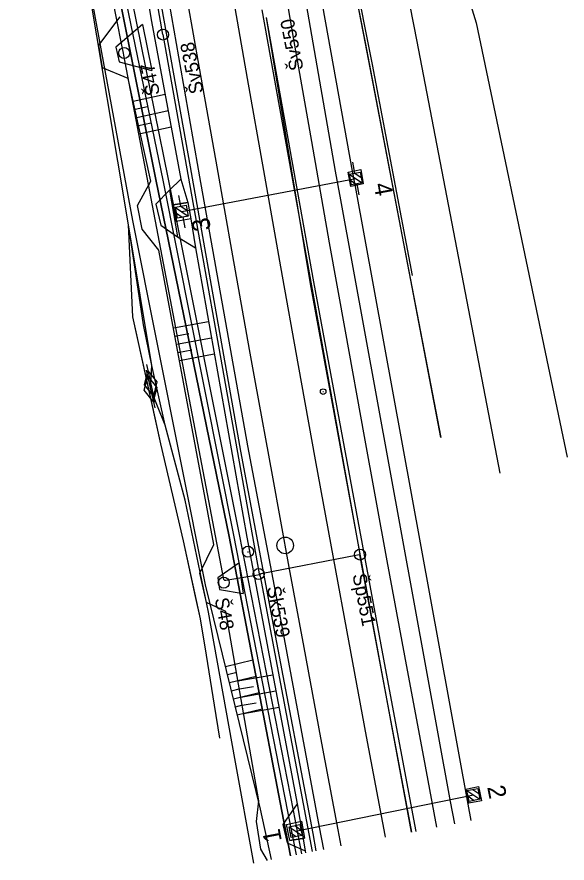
# Model space of a CAD drawing. Extents: x -545736 to -544888, y -1122892 to -1119128.
# Drawn here: x -545053.2 to -545003.3, y -1122756.6 to -1122679.8 of the extents above; entities that cross this region are included whole.
import ezdxf

# ---------------------------------------------------------------- set-up
doc = ezdxf.new("R2010")
doc.units = 0
for name, color, linetype in [('Vrstva 1', 7, 'Continuous'), ('Vrstva 1 - Koleje', 7, 'Continuous'), ('Vrstva 11 - Trakce', 7, 'Continuous'), ('Vrstva 12', 7, 'Continuous'), ('Vrstva 12 - Trakce zaklady', 7, 'Continuous'), ('Vrstva 13', 7, 'Continuous'), ('Vrstva 19 - Staniceni', 7, 'Continuous'), ('Vrstva 28 - zabzar', 7, 'Continuous'), ('Vrstva 31', 7, 'Continuous'), ('Vrstva 32', 7, 'Continuous'), ('Vrstva 4 - Teren - stezky - prechody - plochy', 7, 'Continuous'), ('Vrstva 43', 7, 'Continuous'), ('Vrstva 44', 7, 'Continuous'), ('Vrstva 48', 7, 'Continuous'), ('Vrstva 49', 7, 'Continuous'), ('Vrstva 50', 7, 'Continuous'), ('Vrstva 7 - Namezniky-vystroj', 7, 'Continuous')]:
    doc.layers.add(name, color=color, linetype=linetype)

msp = doc.modelspace()

# ---------------------------------------------------------------- linework, layer by layer
at = {"layer": 'Vrstva 1'}
for points in [[(-545068.904, -1122411.876), (-545066.819, -1122423.364), (-545063.507, -1122440.549), (-545060.331, -1122456.897), (-545057.192, -1122473.275), (-545054.444, -1122488.508), (-545052.57, -1122500.819), (-545051.42, -1122511.592), (-545050.311, -1122520.98), (-545049.375, -1122526.795), (-545046.137, -1122542.925), (-545043.214, -1122557.71), (-545039.903, -1122574.434), (-545036.419, -1122592.255), (-545033.982, -1122604.761), (-545029.871, -1122624.617), (-545027.294, -1122633.968), (-545025.013, -1122641.762), (-545022.676, -1122652.428), (-545020.046, -1122666.027), (-545016.909, -1122682.055), (-545009.383, -1122721.21)], [(-545016.12, -1122665.438), (-545011.513, -1122680.374), (-545003.284, -1122719.736)]]:
    msp.add_lwpolyline(points, dxfattribs=at)
at = {"layer": 'Vrstva 1 - Koleje'}
for points in [[(-545023.767, -1122755), (-545024.043, -1122753.548), (-545025.612, -1122745.204), (-545027.14, -1122737.009), (-545028.487, -1122729.713), (-545030.01, -1122721.384), (-545031.532, -1122712.985), (-545032.069, -1122710.001), (-545033.588, -1122701.505), (-545035.11, -1122692.915), (-545036.637, -1122684.297), (-545038.185, -1122675.556), (-545039.699, -1122666.989), (-545041.211, -1122658.46), (-545042.758, -1122649.711), (-545044.3, -1122641.015), (-545045.323, -1122635.226), (-545046.484, -1122628.653), (-545047.761, -1122621.452), (-545049.274, -1122612.897), (-545050.721, -1122604.725), (-545052.28, -1122595.938)], [(-545015.09, -1122753.302), (-545016.134, -1122747.772), (-545018.009, -1122737.759), (-545019.601, -1122729.15), (-545021.653, -1122717.88), (-545023.38, -1122708.324), (-545024.816, -1122700.316), (-545026.431, -1122691.14), (-545028.048, -1122681.884), (-545029.659, -1122672.557), (-545031.082, -1122664.266), (-545032.373, -1122656.733), (-545033.696, -1122649.053), (-545034.644, -1122643.504), (-545035.403, -1122639.104), (-545036.316, -1122633.811), (-545037.843, -1122624.885), (-545039.388, -1122615.924), (-545041.014, -1122606.453), (-545042.699, -1122596.644)], [(-545019.74, -1122754.212), (-545019.777, -1122754.016), (-545021.46, -1122745.07), (-545023.077, -1122736.395), (-545024.44, -1122729.019), (-545026.088, -1122720.006), (-545027.636, -1122711.45), (-545029.243, -1122702.488), (-545030.788, -1122693.757), (-545032.249, -1122685.43), (-545033.701, -1122677.071), (-545035.124, -1122668.8), (-545035.413, -1122667.129), (-545036.812, -1122658.975), (-545038.248, -1122650.614), (-545039.289, -1122644.538), (-545039.869, -1122641.154), (-545040.66, -1122636.562), (-545041.029, -1122634.405), (-545042.47, -1122626.014), (-545043.93, -1122617.521), (-545045.385, -1122609.05), (-545046.733, -1122601.181)]]:
    msp.add_lwpolyline(points, dxfattribs=at)
at = {"layer": 'Vrstva 11 - Trakce'}
for p, q in [((-545022.53, -1122693.999), (-545022.71, -1122693.012)), ((-545038.214, -1122697.489), (-545022.439, -1122694.487)), ((-545023.017, -1122694.109), (-545021.88, -1122694.893)), ((-545022.921, -1122694.63), (-545022.402, -1122694.989)), ((-545022.523, -1122693.994), (-545021.948, -1122694.391)), ((-545022.351, -1122694.969), (-545022.168, -1122695.962)), ((-545038.305, -1122697.001), (-545038.485, -1122696.014)), ((-545038.298, -1122696.996), (-545037.723, -1122697.393)), ((-545038.792, -1122697.111), (-545037.655, -1122697.895)), ((-545038.696, -1122697.632), (-545038.177, -1122697.991)), ((-545038.126, -1122697.971), (-545037.943, -1122698.964)), ((-545012.362, -1122749.976), (-545011.189, -1122750.758)), ((-545011.843, -1122749.872), (-545011.293, -1122750.239)), ((-545027.903, -1122753.654), (-545011.777, -1122750.369)), ((-545012.262, -1122750.494), (-545011.705, -1122750.865)), ((-545028.484, -1122753.254), (-545027.32, -1122754.05)), ((-545028.389, -1122753.773), (-545027.837, -1122754.15)), ((-545027.963, -1122753.156), (-545027.418, -1122753.529))]:
    msp.add_line(p, q, dxfattribs=at)
for points in [[(-545022.038, -1122693.905), (-545021.857, -1122694.888), (-545022.84, -1122695.069), (-545023.021, -1122694.086)], [(-545037.813, -1122696.907), (-545037.632, -1122697.89), (-545038.615, -1122698.071), (-545038.796, -1122697.088)], [(-545011.385, -1122749.781), (-545011.189, -1122750.761), (-545012.169, -1122750.957), (-545012.365, -1122749.977)], [(-545027.504, -1122753.07), (-545027.319, -1122754.053), (-545028.302, -1122754.238), (-545028.487, -1122753.255)]]:
    msp.add_lwpolyline(points, close=True, dxfattribs=at)
at = {"layer": 'Vrstva 12'}
for points in [[(-545026.22, -1122658.509), (-545024.157, -1122669.139), (-545021.595, -1122682.153), (-545018.115, -1122700.386), (-545014.754, -1122717.969)], [(-545017.292, -1122703.282), (-545020.935, -1122684.162), (-545024.277, -1122667.282), (-545025.839, -1122658.306), (-545026.086, -1122658.352)], [(-545024.136, -1122669.136), (-545021.579, -1122682.243), (-545018.116, -1122700.384), (-545014.728, -1122717.956)]]:
    msp.add_lwpolyline(points, dxfattribs=at)
at = {"layer": 'Vrstva 12 - Trakce zaklady'}
for p, q in [((-545023.134, -1122693.91), (-545021.985, -1122693.681)), ((-545021.76, -1122694.96), (-545022.902, -1122695.206)), ((-545037.682, -1122696.647), (-545039.011, -1122696.884)), ((-545037.41, -1122698.127), (-545038.727, -1122698.372)), ((-545012.473, -1122749.852), (-545011.314, -1122749.611)), ((-545011.056, -1122750.9), (-545012.203, -1122751.117)), ((-545028.422, -1122754.51), (-545028.737, -1122753.043)), ((-545028.422, -1122754.51), (-545027.087, -1122754.284))]:
    msp.add_line(p, q, dxfattribs=at)
for points in [[(-545022.902, -1122695.206), (-545023.134, -1122693.91), (-545021.985, -1122693.681), (-545021.76, -1122694.96), (-545022.902, -1122695.206)], [(-545023.134, -1122693.91), (-545023.134, -1122693.91), (-545022.902, -1122695.206), (-545022.902, -1122695.206)], [(-545021.985, -1122693.681), (-545021.985, -1122693.681), (-545021.76, -1122694.96), (-545021.76, -1122694.96)], [(-545037.682, -1122696.647), (-545037.41, -1122698.127), (-545038.727, -1122698.372), (-545039.011, -1122696.884), (-545037.682, -1122696.647)], [(-545037.682, -1122696.647), (-545037.682, -1122696.647), (-545037.41, -1122698.127), (-545037.41, -1122698.127)], [(-545012.203, -1122751.117), (-545012.473, -1122749.852), (-545011.314, -1122749.611), (-545011.056, -1122750.9), (-545012.203, -1122751.117)], [(-545012.473, -1122749.852), (-545012.473, -1122749.852), (-545012.203, -1122751.117), (-545012.203, -1122751.117)], [(-545011.314, -1122749.611), (-545011.314, -1122749.611), (-545011.056, -1122750.9), (-545011.056, -1122750.9)], [(-545027.375, -1122752.749), (-545027.087, -1122754.284), (-545028.422, -1122754.51), (-545028.737, -1122753.043), (-545027.375, -1122752.749)], [(-545028.737, -1122753.043), (-545028.737, -1122753.043), (-545027.375, -1122752.749), (-545027.375, -1122752.749)], [(-545027.375, -1122752.749), (-545027.087, -1122754.284), (-545027.087, -1122754.284)]]:
    msp.add_lwpolyline(points, dxfattribs=at)
at = {"layer": 'Vrstva 13'}
for points in [[(-545028.35, -1122755.897), (-545029.145, -1122751.861), (-545033.916, -1122726.946), (-545040.565, -1122694.58), (-545045.437, -1122670.217), (-545050.32, -1122646.168), (-545054.473, -1122623.814), (-545058.217, -1122603.978), (-545063.836, -1122576.435), (-545069.59, -1122547.465), (-545075.408, -1122519.018), (-545078.686, -1122503.072), (-545078.31, -1122502.943)], [(-545027.819, -1122755.793), (-545028.599, -1122751.872), (-545033.511, -1122726.819), (-545039.921, -1122694.648), (-545044.959, -1122670.154), (-545049.898, -1122646.069), (-545054.001, -1122623.766), (-545057.758, -1122603.891), (-545063.364, -1122576.321), (-545069.202, -1122547.386), (-545075.005, -1122518.95), (-545078.31, -1122502.943), (-545077.905, -1122502.754), (-545074.587, -1122518.877), (-545068.787, -1122547.323), (-545062.931, -1122576.272), (-545057.246, -1122603.793), (-545053.518, -1122623.679), (-545049.43, -1122646.062), (-545044.427, -1122670.103), (-545039.459, -1122694.557), (-545033.025, -1122726.769), (-545028.137, -1122751.773), (-545027.357, -1122755.702)]]:
    msp.add_lwpolyline(points, dxfattribs=at)
at = {"layer": 'Vrstva 19 - Staniceni'}
msp.add_circle((-545028.846, -1122727.751), 0.75, dxfattribs=at)
at = {"layer": 'Vrstva 28 - zabzar'}
for p, q in [((-545041.423, -1122711.347), (-545040.657, -1122714.753)), ((-545039.73, -1122716.86), (-545040.95, -1122711.44)), ((-545041.608, -1122713.178), (-545041.296, -1122711.915)), ((-545041.443, -1122711.857), (-545040.677, -1122715.263)), ((-545041.296, -1122711.915), (-545040.472, -1122712.922)), ((-545041.628, -1122713.688), (-545041.316, -1122712.425)), ((-545041.316, -1122712.425), (-545040.492, -1122713.432)), ((-545040.472, -1122712.922), (-545040.784, -1122714.185)), ((-545040.804, -1122714.695), (-545041.628, -1122713.688)), ((-545040.784, -1122714.185), (-545041.608, -1122713.178)), ((-545040.492, -1122713.432), (-545040.804, -1122714.695))]:
    msp.add_line(p, q, dxfattribs=at)
for points in [[(-545031.702, -1122756.553), (-545033.41, -1122747.06), (-545035.8, -1122733.81), (-545037.91, -1122723.65), (-545039.73, -1122716.86), (-545041.06, -1122713.56), (-545041.04, -1122713.05), (-545040.95, -1122711.44), (-545041.68, -1122707.74), (-545043.05, -1122698.7), (-545046.9, -1122675.76), (-545050.11, -1122660.02), (-545051.04, -1122658.97), (-545052.61, -1122653.49), (-545054.9, -1122643.24), (-545056.97, -1122632.39), (-545059.36, -1122618.98), (-545062.05, -1122603.96), (-545065.13, -1122586.61)], [(-545034.78, -1122745.23), (-545035.26, -1122742.24), (-545035.97, -1122737.69), (-545036.53, -1122734.41), (-545038.07, -1122727.35), (-545040.12, -1122718.53), (-545042.66, -1122707.03), (-545043.05, -1122698.7)]]:
    msp.add_lwpolyline(points, dxfattribs=at)
at = {"layer": 'Vrstva 31'}
msp.add_lwpolyline([(-545031.702, -1122756.553), (-545033.41, -1122747.06), (-545035.8, -1122733.81), (-545037.91, -1122723.65), (-545039.73, -1122716.86), (-545040.95, -1122711.44), (-545043.05, -1122698.7), (-545046.9, -1122675.76), (-545050.11, -1122660.02), (-545051.04, -1122658.97), (-545052.61, -1122653.49), (-545054.9, -1122643.24), (-545056.97, -1122632.39), (-545059.36, -1122618.98), (-545062.05, -1122603.96), (-545065.13, -1122586.61)], dxfattribs=at)
at = {"layer": 'Vrstva 32'}
for points in [[(-545031.702, -1122756.553), (-545033.41, -1122747.06), (-545035.8, -1122733.81), (-545037.91, -1122723.65), (-545039.73, -1122716.86), (-545040.95, -1122711.44), (-545041.68, -1122707.74), (-545043.05, -1122698.7), (-545046.9, -1122675.76), (-545050.11, -1122660.02), (-545051.04, -1122658.97), (-545052.61, -1122653.49), (-545054.9, -1122643.24), (-545056.97, -1122632.39), (-545059.36, -1122618.98), (-545062.05, -1122603.96), (-545065.13, -1122586.61)], [(-545034.78, -1122745.23), (-545035.26, -1122742.24), (-545035.97, -1122737.69), (-545036.53, -1122734.41), (-545038.07, -1122727.35), (-545040.12, -1122718.53), (-545040.85, -1122715.22), (-545042.66, -1122707.03), (-545043.05, -1122698.7)], [(-545034.78, -1122745.23), (-545035.26, -1122742.24), (-545035.97, -1122737.69), (-545036.53, -1122734.41), (-545036.97, -1122732.37), (-545038.07, -1122727.35), (-545040.12, -1122718.53), (-545040.85, -1122715.22), (-545042.66, -1122707.03), (-545043.05, -1122698.7)]]:
    msp.add_lwpolyline(points, dxfattribs=at)
at = {"layer": 'Vrstva 4 - Teren - stezky - prechody - plochy'}
for points in [[(-545070.278, -1122429.488), (-545064.72, -1122457.892), (-545060.382, -1122480.861), (-545059.861, -1122483.446), (-545053.003, -1122522.259), (-545052.753, -1122523.663), (-545048.917, -1122544.179), (-545042.47, -1122579.486), (-545042.186, -1122581.244), (-545032.733, -1122635.783), (-545027.941, -1122665.049), (-545022.786, -1122693.812), (-545022.502, -1122695.225), (-545012.285, -1122751.226), (-545012.008, -1122752.698)], [(-545071.756, -1122430.223), (-545066.205, -1122458.377), (-545061.37, -1122483.517), (-545053.92, -1122523.598), (-545044.041, -1122579.762), (-545034.681, -1122633.788), (-545029.212, -1122665.663), (-545024.312, -1122693.834), (-545023.844, -1122696.43), (-545013.894, -1122750.973), (-545013.506, -1122752.991)], [(-545026.025, -1122755.442), (-545026.304, -1122753.88), (-545029.721, -1122735.926), (-545032.88, -1122719.209), (-545037.444, -1122693.434), (-545042.852, -1122663.259), (-545048.752, -1122629.61), (-545054.166, -1122599.069), (-545058.27, -1122575.78), (-545066.012, -1122532.259), (-545072.56, -1122496.705), (-545074.668, -1122485.241), (-545074.197, -1122483.96)], [(-545026.025, -1122755.442), (-545026.304, -1122753.88), (-545029.721, -1122735.926), (-545032.88, -1122719.209), (-545037.444, -1122693.434), (-545042.852, -1122663.259), (-545048.752, -1122629.61), (-545054.166, -1122599.069), (-545058.27, -1122575.78), (-545066.012, -1122532.259), (-545072.56, -1122496.705), (-545074.668, -1122485.241), (-545074.197, -1122483.96)], [(-545025.346, -1122755.309), (-545025.726, -1122753.286), (-545028.91, -1122736.209), (-545032.227, -1122718.736), (-545036.575, -1122694.341), (-545042.092, -1122662.868), (-545048.101, -1122629.185), (-545053.335, -1122599.479), (-545057.782, -1122575.273), (-545065.086, -1122534.093), (-545074.197, -1122483.96)], [(-545047.771, -1122640.461), (-545043.536, -1122665.151), (-545040.958, -1122680.252), (-545038.303, -1122694.554), (-545037.682, -1122696.647), (-545037.41, -1122698.127), (-545036.991, -1122700.776), (-545032.31, -1122726.991), (-545027.758, -1122751.171), (-545027.043, -1122755.43), (-545027.005, -1122755.633)], [(-545030.564, -1122679.902), (-545026.583, -1122704.046), (-545020.166, -1122738.878), (-545017.437, -1122753.761)], [(-545030.564, -1122679.902), (-545026.275, -1122703.859), (-545019.783, -1122738.886), (-545017.012, -1122753.678)]]:
    msp.add_lwpolyline(points, dxfattribs=at)
at = {"layer": 'Vrstva 43'}
for centre in [(-545039.92, -1122681.436), (-545043.448, -1122683.102), (-545022.066, -1122728.582), (-545031.258, -1122730.345), (-545034.412, -1122731.127)]:
    msp.add_circle(centre, 0.5, dxfattribs=at)
at = {"layer": 'Vrstva 44'}
for points in [[(-545034.331, -1122730.946), (-545034.408, -1122730.851), (-545043.487, -1122683.296), (-545043.501, -1122683.128), (-545043.647, -1122682.406), (-545053.171, -1122634.139), (-545053.168, -1122633.456), (-545053.287, -1122633.279), (-545063.238, -1122586.146)], [(-545039.928, -1122681.441), (-545048.45, -1122633.043), (-545048.622, -1122632.851)], [(-545030.949, -1122679.203), (-545022.122, -1122728.385), (-545022.084, -1122728.591)], [(-545039.928, -1122681.441), (-545031.208, -1122730.343), (-545031.174, -1122730.41)], [(-545022.084, -1122728.591), (-545022.284, -1122728.621), (-545031.039, -1122730.317), (-545031.174, -1122730.41), (-545031.52, -1122730.469), (-545034.225, -1122730.925), (-545034.331, -1122730.946)], [(-545017.35, -1122753.744), (-545022.048, -1122728.751), (-545022.084, -1122728.591)], [(-545026.368, -1122755.509), (-545031.074, -1122730.527), (-545031.174, -1122730.41)]]:
    msp.add_lwpolyline(points, dxfattribs=at)
at = {"layer": 'Vrstva 48'}
for p, q in [((-545042.628, -1122687.478), (-545039.736, -1122686.835)), ((-545042.465, -1122688.21), (-545041.319, -1122687.955)), ((-545042.302, -1122688.942), (-545039.462, -1122688.31)), ((-545042.139, -1122689.674), (-545041.014, -1122689.424)), ((-545041.977, -1122690.406), (-545039.188, -1122689.786)), ((-545038.988, -1122708.038), (-545035.801, -1122707.442)), ((-545038.85, -1122708.775), (-545037.578, -1122708.537)), ((-545038.713, -1122709.512), (-545035.537, -1122708.918)), ((-545038.575, -1122710.249), (-545037.307, -1122710.012)), ((-545038.437, -1122710.987), (-545035.273, -1122710.395)), ((-545034.257, -1122738.738), (-545031.774, -1122738.13)), ((-545034.078, -1122739.466), (-545033.345, -1122739.287)), ((-545033.9, -1122740.195), (-545031.492, -1122739.605)), ((-545033.13, -1122740.026), (-545029.96, -1122739.475)), ((-545033.722, -1122740.923), (-545033.01, -1122740.749)), ((-545033.002, -1122740.765), (-545031.73, -1122740.544)), ((-545033.543, -1122741.652), (-545031.209, -1122741.08)), ((-545032.873, -1122741.504), (-545029.682, -1122740.949)), ((-545033.365, -1122742.38), (-545032.676, -1122742.212)), ((-545032.745, -1122742.243), (-545031.464, -1122742.02)), ((-545033.186, -1122743.109), (-545030.927, -1122742.555)), ((-545032.616, -1122742.982), (-545029.405, -1122742.423))]:
    msp.add_line(p, q, dxfattribs=at)
at = {"layer": 'Vrstva 49'}
for points in [[(-545092.575, -1122433.846), (-545090.002, -1122441.276), (-545089.045, -1122447.984), (-545086.196, -1122453.537), (-545081.831, -1122476.339), (-545078.686, -1122503.072), (-545075.408, -1122519.018), (-545069.59, -1122547.465), (-545063.836, -1122576.435), (-545058.217, -1122603.978), (-545054.473, -1122623.814), (-545050.32, -1122646.168), (-545045.437, -1122670.217), (-545040.565, -1122694.58), (-545033.916, -1122726.946), (-545029.145, -1122751.861), (-545028.35, -1122755.897)], [(-545075.964, -1122483.68), (-545075.6, -1122485.236), (-545072.758, -1122500.963), (-545068.047, -1122526.836), (-545062.05, -1122559.844), (-545057.718, -1122584.534), (-545053.739, -1122607.276), (-545050.173, -1122627.441), (-545051.791, -1122631.205), (-545050.172, -1122639.206), (-545047.771, -1122640.461), (-545043.536, -1122665.151), (-545040.958, -1122680.252), (-545038.303, -1122694.554), (-545037.682, -1122696.647), (-545037.41, -1122698.127), (-545036.991, -1122700.776), (-545032.31, -1122726.991), (-545027.758, -1122751.171), (-545029.064, -1122753.063), (-545028.667, -1122754.707), (-545027.043, -1122755.43), (-545027.005, -1122755.633)], [(-545030.095, -1122756.238), (-545031.088, -1122751.676), (-545036.07, -1122731.335), (-545042.669, -1122698.278), (-545047.624, -1122671.381), (-545050.951, -1122653.263), (-545050.168, -1122651.203), (-545050.566, -1122649.119), (-545051.466, -1122646.826), (-545055.136, -1122631.975), (-545056.341, -1122626.638), (-545059.286, -1122607.868), (-545065.622, -1122576.388)], [(-545030.442, -1122756.306), (-545031.065, -1122755.28), (-545031.436, -1122752.782), (-545031.234, -1122750.922), (-545034.225, -1122733.737), (-545035.987, -1122732.928), (-545036.578, -1122730.28), (-545035.314, -1122727.683), (-545040.307, -1122700.987), (-545041.826, -1122699.066), (-545042.252, -1122696.941), (-545041.016, -1122694.725), (-545043.084, -1122685.427), (-545045.403, -1122684.437), (-545045.757, -1122682.389), (-545043.813, -1122679.833)], [(-545041.778, -1122680.51), (-545044.216, -1122682.572), (-545043.891, -1122683.897), (-545040.939, -1122684.7)], [(-545041.778, -1122680.51), (-545040.939, -1122684.7)], [(-545038.303, -1122694.554), (-545039.344, -1122695.533), (-545038.625, -1122699.765), (-545036.991, -1122700.776)], [(-545039.344, -1122695.533), (-545040.57, -1122696.822), (-545040.135, -1122698.729), (-545038.625, -1122699.765)], [(-545033.043, -1122729.347), (-545034.96, -1122730.688), (-545034.805, -1122731.754), (-545032.662, -1122732.115)], [(-545033.043, -1122729.347), (-545032.662, -1122732.115)]]:
    msp.add_lwpolyline(points, dxfattribs=at)
at = {"layer": 'Vrstva 50'}
msp.add_line((-545025.427, -1122713.807), (-545025.377, -1122713.807), dxfattribs=at)
msp.add_circle((-545025.402, -1122713.807), 0.25, dxfattribs=at)
at = {"layer": 'Vrstva 7 - Namezniky-vystroj'}
msp.add_line((-545032.272, -1122728.321), (-545032.172, -1122728.321), dxfattribs=at)
msp.add_circle((-545032.222, -1122728.321), 0.5, dxfattribs=at)

# ---------------------------------------------------------------- texts
at = {"layer": 'Vrstva 11 - Trakce'}
for s, rotation, p in [('4', 280.41383, (-545020.831, -1122695.006)), ('3', 100.41383, (-545035.568, -1122699.108)), ('2', 281.31848, (-545010.536, -1122749.66)), ('1', 100.62642, (-545029.144, -1122754.524))]:
    msp.add_text(s, height=1.6, rotation=rotation, dxfattribs=at).set_placement(p)
at = {"layer": 'Vrstva 43'}
for s, rotation, p in [('Šv550', 101.03229, (-545027.176, -1122684.57)), ('Šv538', 101.03229, (-545036.248, -1122686.676)), ('Š47', 101.16216, (-545040.201, -1122686.847)), ('Šp551', 281.03229, (-545022.752, -1122730.422)), ('Šk539', 281.03229, (-545030.515, -1122731.553)), ('Š48', 280.8086, (-545035.245, -1122732.604))]:
    msp.add_text(s, height=1.25, rotation=rotation, dxfattribs=at).set_placement(p)

doc.saveas('drawing.dxf')
